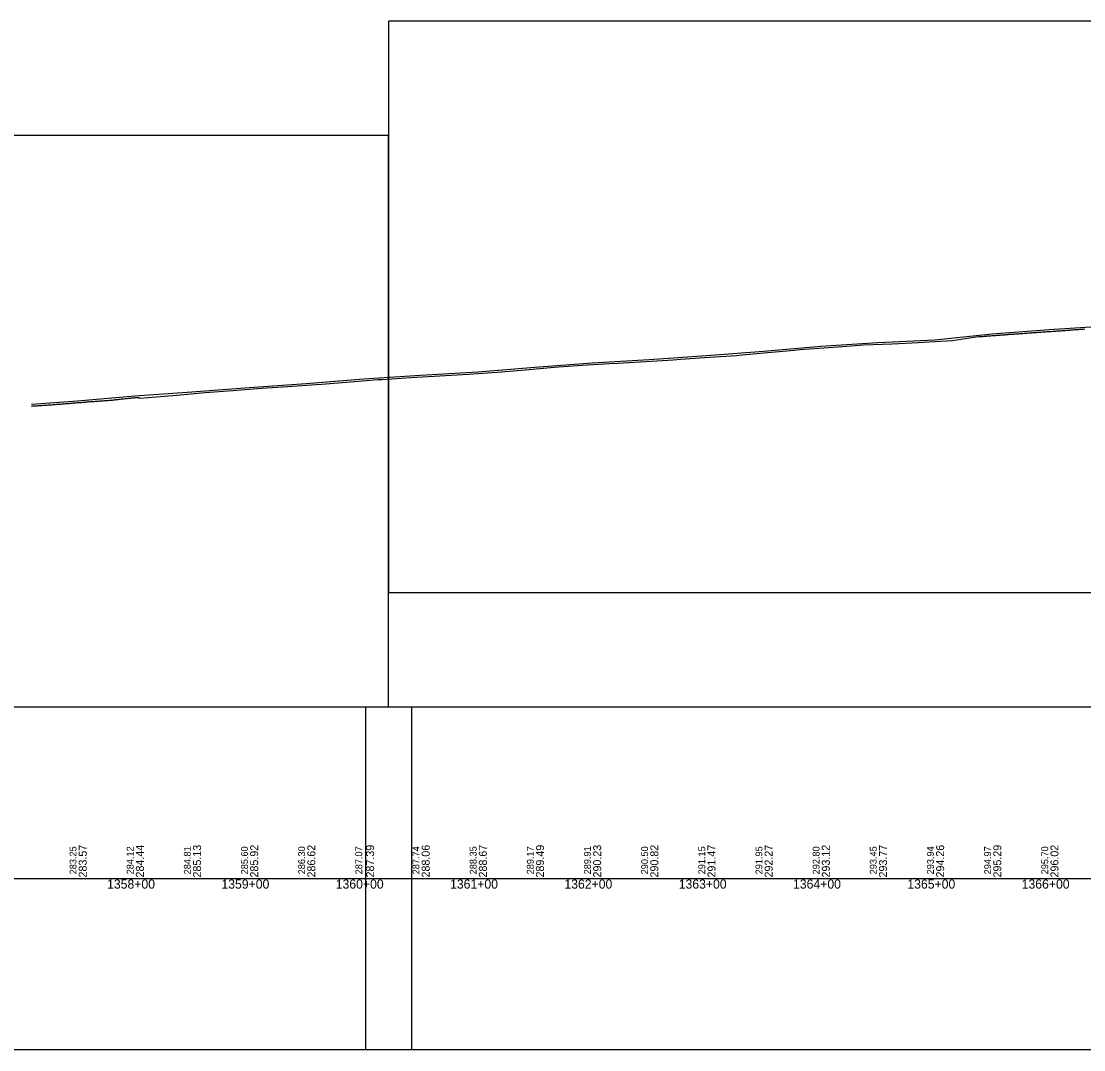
# Model space of a CAD drawing. Extents: x 2898 to 49495, y -15038 to -13538.
# Drawn here: x 25154 to 26083, y -15038 to -14138 of the extents above; entities that cross this region are included whole.
import ezdxf

# ---------------------------------------------------------------- set-up
doc = ezdxf.new("R2010")
doc.units = 0
for name, color, linetype in [('RD_DDB_Profile_EX', 7, 'Continuous'), ('RD_DDB_Profile_PR', 7, 'Continuous'), ('RD_DDB_StaTX', 7, 'Continuous'), ('RD_DDB_StripGrade', 7, 'Continuous'), ('RD_GPK_Profile_Cell', 7, 'Continuous'), ('RD_SHT_ShtClip', 7, 'Continuous')]:
    doc.layers.add(name, color=color, linetype=linetype)

msp = doc.modelspace()

# ---------------------------------------------------------------- linework, layer by layer
at = {"layer": 'RD_DDB_Profile_EX'}
for points in [[(25364.2, -14459.66), (25387.31, -14458.07), (25412.01, -14456.38), (25417.01, -14455.99), (25441.94, -14454.01), (25466.36, -14452.08), (25469.61, -14451.87), (25494.76, -14450.33), (25520.21, -14448.72), (25545.33, -14447.19), (25570.47, -14445.68), (25595.11, -14443.4), (25620.26, -14441.06), (25644.86, -14439.45), (25668.66, -14437.89), (25675.52, -14437.52), (25700.55, -14436.11), (25724.49, -14434.74), (25731.04, -14434.27), (25756.26, -14432.5), (25779.67, -14430.88), (25781.85, -14430.71), (25807.01, -14428.37), (25830.36, -14426.18), (25835.24, -14425.84), (25860.39, -14423.91), (25883.7, -14422.09), (25890.88, -14421.74), (25916.03, -14420.64), (25938.93, -14419.64), (25943.45, -14419.36), (25968.8, -14417.82), (25991.32, -14414.47), (25992.34, -14414.42), (25993.34, -14414.33), (25994.33, -14414.31), (25995.34, -14414.21), (25996.34, -14414.12), (25997.33, -14414.07), (25998.33, -14413.97), (25999.33, -14413.87), (26000.34, -14413.87), (26001.34, -14413.81), (26002.33, -14413.63), (26003.33, -14413.59), (26004.34, -14413.57), (26005.33, -14413.47), (26006.33, -14413.38), (26007.33, -14413.28), (26008.33, -14413.2), (26009.33, -14413.15), (26010.33, -14413.06), (26011.33, -14412.97), (26012.33, -14412.88), (26013.34, -14412.79), (26014.33, -14412.74), (26015.33, -14412.64), (26016.33, -14412.57), (26017.33, -14412.52), (26018.33, -14412.42), (26019.33, -14412.37), (26020.33, -14412.32), (26021.33, -14412.2), (26022.33, -14412.15), (26023.33, -14412.11), (26024.33, -14412.05), (26025.33, -14411.96), (26026.33, -14411.9), (26027.33, -14411.81), (26028.33, -14411.71), (26029.33, -14411.66), (26030.33, -14411.61), (26031.33, -14411.51), (26032.33, -14411.41), (26033.33, -14411.36), (26034.33, -14411.3), (26035.33, -14411.21), (26036.33, -14411.12), (26037.33, -14411.06), (26038.33, -14411), (26039.33, -14410.91), (26040.33, -14410.86), (26041.33, -14410.8), (26042.33, -14410.74), (26043.33, -14410.65), (26044.33, -14410.59), (26045.33, -14410.49), (26046.33, -14410.45), (26047.33, -14410.35), (26048.33, -14410.25), (26049.33, -14410.21), (26050.33, -14410.12), (26051.33, -14410.01), (26052.33, -14410), (26053.33, -14409.95), (26054.33, -14409.87), (26055.33, -14409.82), (26056.33, -14409.73), (26057.33, -14409.69), (26058.33, -14409.63), (26059.33, -14409.54)], [(26059.33, -14409.54), (26060.33, -14409.43), (26061.33, -14409.36), (26062.33, -14409.23), (26063.33, -14409.23), (26064.33, -14409.14), (26065.33, -14409.08), (26066.33, -14409), (26067.33, -14408.94), (26068.33, -14408.89), (26069.33, -14408.8), (26070.33, -14408.73), (26071.33, -14408.7), (26072.33, -14408.62), (26073.33, -14408.52), (26074.33, -14408.43), (26075.33, -14408.34), (26076.33, -14408.3), (26077.33, -14408.24), (26078.33, -14408.18), (26079.33, -14408.09), (26080.33, -14408.02), (26081.33, -14407.91), (26082.33, -14407.85), (26083.33, -14407.82), (26084.33, -14407.75)], [(25163.14, -14475.17), (25163.95, -14475.13), (25164.94, -14475.04), (25165.95, -14475), (25166.94, -14474.95), (25167.94, -14474.89), (25168.94, -14474.79), (25169.93, -14474.74), (25170.94, -14474.69), (25171.93, -14474.59), (25172.93, -14474.54), (25173.93, -14474.49), (25174.92, -14474.44), (25175.93, -14474.39), (25176.92, -14474.28), (25177.92, -14474.23), (25178.92, -14474.13), (25179.92, -14474.03), (25180.92, -14473.98), (25181.92, -14473.93), (25182.91, -14473.83), (25183.92, -14473.78), (25184.91, -14473.63), (25185.91, -14473.58), (25186.91, -14473.58), (25187.9, -14473.53), (25188.91, -14473.43), (25189.9, -14473.33), (25190.9, -14473.28), (25191.89, -14473.18), (25192.9, -14473.07), (25193.9, -14472.97), (25194.89, -14472.92), (25195.89, -14472.82), (25196.9, -14472.77), (25197.89, -14472.67), (25198.9, -14472.57), (25199.89, -14472.47), (25200.89, -14472.37), (25201.9, -14472.32), (25202.89, -14472.22), (25203.89, -14472.22), (25204.9, -14472.12), (25205.89, -14472.07), (25206.89, -14471.97), (25207.9, -14471.87), (25208.89, -14471.77), (25209.89, -14471.72), (25210.9, -14471.62), (25211.89, -14471.52), (25212.89, -14471.47), (25213.89, -14471.32), (25214.89, -14471.27), (25215.9, -14471.27), (25216.89, -14471.17), (25217.89, -14471.07), (25218.9, -14471.02), (25219.89, -14470.97), (25220.89, -14470.87), (25221.89, -14470.82), (25222.89, -14470.72), (25223.89, -14470.67), (25224.89, -14470.52), (25225.89, -14470.52), (25226.89, -14470.47), (25227.89, -14470.37), (25228.89, -14470.32), (25229.9, -14470.22), (25230.89, -14470.12), (25231.89, -14470.02), (25232.89, -14469.97), (25233.89, -14469.92), (25234.89, -14469.77), (25235.88, -14469.62), (25236.89, -14469.52), (25237.89, -14469.47), (25238.89, -14469.32), (25239.89, -14469.27), (25240.89, -14469.13), (25241.89, -14469.02), (25242.89, -14468.92), (25243.89, -14468.78), (25244.89, -14468.67), (25245.89, -14468.62), (25246.89, -14468.53), (25247.89, -14468.42), (25248.89, -14468.32), (25249.88, -14468.22), (25250.89, -14468.13), (25251.89, -14468.02), (25252.89, -14467.92), (25253.89, -14467.82), (25254.89, -14467.73), (25255.88, -14467.67), (25256.88, -14467.62), (25257.92, -14468.27), (25265.16, -14467.65), (25290.13, -14465.53), (25315.12, -14463.41), (25339.19, -14461.57), (25364.2, -14459.66)]]:
    msp.add_lwpolyline(points, dxfattribs=at)
at = {"layer": 'RD_DDB_Profile_PR'}
msp.add_lwpolyline([(25163.14, -14473.64), (25203.38, -14470.62), (25253.38, -14466.27), (25303.38, -14462.81), (25353.38, -14458.89), (25403.38, -14455.37), (25453.38, -14451.51), (25503.38, -14448.19), (25553.38, -14445.11), (25603.38, -14441.03), (25653.38, -14437.29), (25703.38, -14434.35), (25753.38, -14431.1), (25803.38, -14427.11), (25853.38, -14422.85), (25903.38, -14419.59), (25953.38, -14417.16), (26003.38, -14411.99), (26053.38, -14408.35), (26103.38, -14404.87)], dxfattribs=at)
at = {"layer": 'RD_GPK_Profile_Cell'}
msp.add_line((2976.05, -14888.47), (48721.13, -14888.47), dxfattribs=at)
at = {"layer": 'RD_SHT_ShtClip'}
for points in [[(25475.38, -14138.47), (25475.38, -14638.47), (26975.38, -14638.47), (26975.38, -14638.47), (26975.38, -14138.47), (26975.38, -14138.47)], [(23975.38, -14238.47), (23975.38, -14738.47), (25475.38, -14738.47), (25475.38, -14738.47), (25475.38, -14238.47), (25475.38, -14238.47)], [(23955.38, -14738.47), (25495.38, -14738.47), (25495.38, -15038.47), (23955.38, -15038.47)], [(25455.38, -14738.47), (26995.38, -14738.47), (26995.38, -15038.47), (25455.38, -15038.47)]]:
    msp.add_lwpolyline(points, close=True, dxfattribs=at)

# ---------------------------------------------------------------- texts
at = {"layer": 'RD_DDB_StaTX'}
for s, p in [('1358+00', (25229.18, -14897.47)), ('1359+00', (25329.18, -14897.47)), ('1360+00', (25429.18, -14897.47)), ('1361+00', (25529.18, -14897.47)), ('1362+00', (25629.18, -14897.47)), ('1363+00', (25729.18, -14897.47)), ('1364+00', (25829.18, -14897.47)), ('1365+00', (25929.18, -14897.47)), ('1366+00', (26029.18, -14897.47))]:
    msp.add_text(s, height=8, dxfattribs=at).set_placement(p)
at = {"layer": 'RD_DDB_StripGrade'}
for s, height, p in [('283.25', 6, (25202.38, -14884.98)), ('283.57', 7, (25211.38, -14887.72)), ('284.12', 6, (25252.38, -14884.98)), ('284.44', 7, (25261.38, -14887.72)), ('284.81', 6, (25302.38, -14884.98)), ('285.13', 7, (25311.38, -14887.72)), ('285.60', 6, (25352.38, -14884.98)), ('285.92', 7, (25361.38, -14887.72)), ('286.30', 6, (25402.38, -14884.98)), ('286.62', 7, (25411.38, -14887.72)), ('287.07', 6, (25452.38, -14884.98)), ('287.39', 7, (25462.76, -14887.72)), ('287.74', 6, (25502.38, -14884.98)), ('288.06', 7, (25511.38, -14887.72)), ('288.35', 6, (25552.38, -14884.98)), ('288.67', 7, (25561.38, -14887.72)), ('289.17', 6, (25602.38, -14884.98)), ('289.49', 7, (25611.38, -14887.72)), ('289.91', 6, (25652.38, -14884.98)), ('290.23', 7, (25661.38, -14887.72)), ('290.50', 6, (25702.38, -14884.98)), ('290.82', 7, (25711.38, -14887.72)), ('291.15', 6, (25752.38, -14884.98)), ('291.47', 7, (25761.38, -14887.72)), ('291.95', 6, (25802.38, -14884.98)), ('292.27', 7, (25811.38, -14887.72)), ('292.80', 6, (25852.38, -14884.98)), ('293.12', 7, (25861.38, -14887.72)), ('293.45', 6, (25902.38, -14884.98)), ('293.77', 7, (25911.38, -14887.72)), ('293.94', 6, (25952.38, -14884.98)), ('294.26', 7, (25961.38, -14887.72)), ('294.97', 6, (26002.38, -14884.98)), ('295.29', 7, (26011.38, -14887.72)), ('295.70', 6, (26052.38, -14884.98)), ('296.02', 7, (26061.38, -14887.72))]:
    msp.add_text(s, height=height, rotation=90, dxfattribs=at).set_placement(p)

doc.saveas('drawing.dxf')
